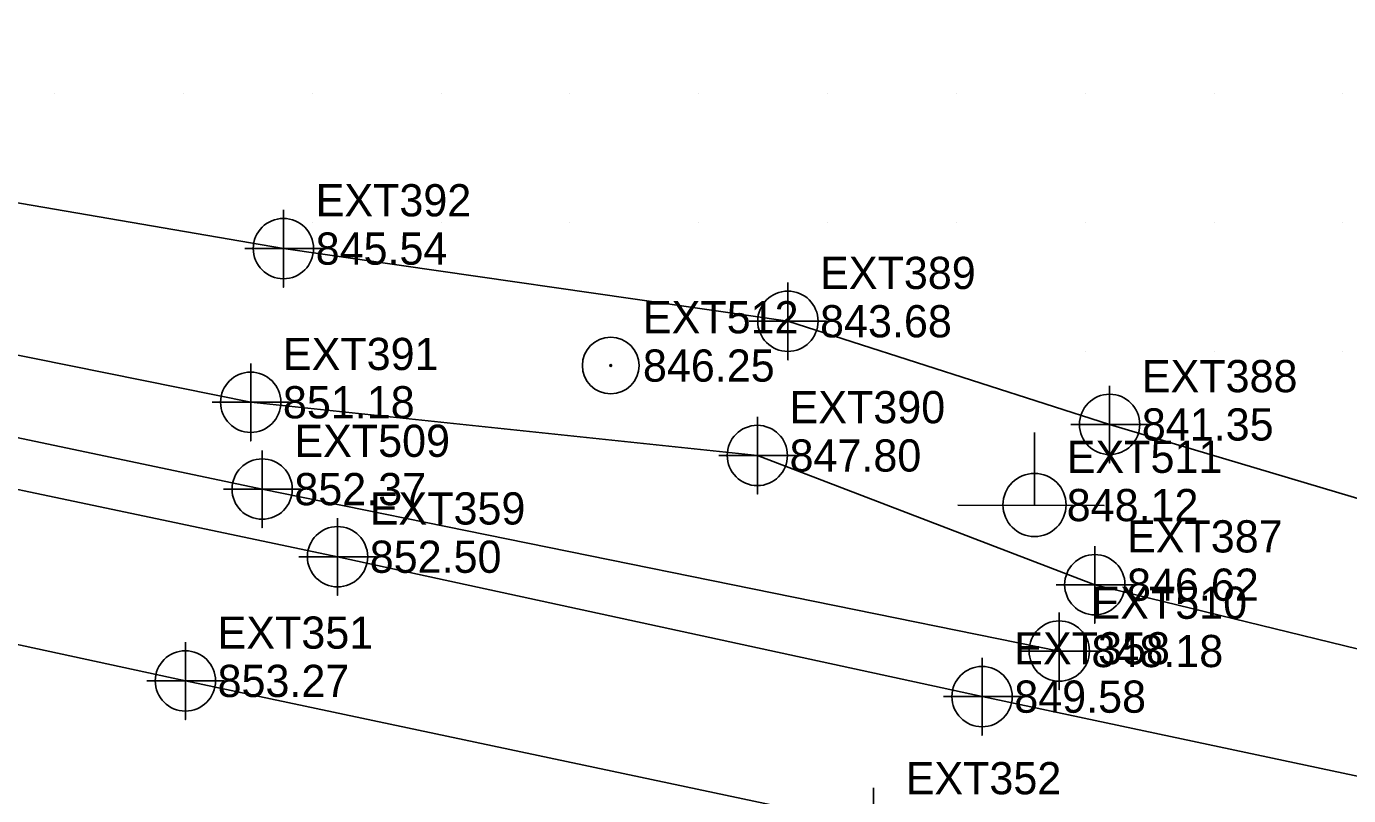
# Model space of a CAD drawing. Extents: x 1762120 to 1766775, y 709485 to 712965.
# Drawn here: x 1762807.8 to 1762910.4, y 712625.5 to 712685.2 of the extents above; entities that cross this region are included whole.
import ezdxf

# ---------------------------------------------------------------- set-up
doc = ezdxf.new("R2010")
doc.units = 0
for name, color, linetype in [('Exist DTM Breakline', 7, 'Continuous'), ('Exist DTM Breakline Cogo Elevation', 7, 'Continuous'), ('Exist DTM Breakline Cogo Number', 7, 'Continuous'), ('Exist DTM Breakline Cogo Point CELL', 7, 'Continuous'), ('Exist DTM Crownline', 7, 'Continuous'), ('Exist DTM Crownline Cogo Elevation', 7, 'Continuous'), ('Exist DTM Crownline Cogo Number', 7, 'Continuous'), ('Exist DTM Crownline Cogo Point CELL', 7, 'Continuous'), ('Exist DTM Drainline', 7, 'Continuous'), ('Exist DTM Drainline Cogo Elevation', 7, 'Continuous'), ('Exist DTM Drainline Cogo Number', 7, 'Continuous'), ('Exist DTM Drainline Cogo Point CELL', 7, 'Continuous'), ('Exist DTM QL2 LIDAR Elevation Point', 7, 'Continuous'), ('Exist Property Iron Pin CELL', 7, 'Continuous'), ('Exist Property Iron Pin Cogo Elevation', 7, 'Continuous'), ('Exist Property Iron Pin Cogo Number', 7, 'Continuous'), ('Exist Roads EOP', 7, 'Continuous'), ('Exist Roads EOP Cogo Elevation', 7, 'Continuous'), ('Exist Roads EOP Cogo Number', 7, 'Continuous'), ('Exist Roads EOP Cogo Point CELL', 7, 'Continuous'), ('Exist Utilities Gas UG Line SUE LOS C', 7, 'Continuous'), ('Exist Utilities Gas UG Line SUE LOS C Cogo Elevation', 7, 'Continuous'), ('Exist Utilities Gas UG Line SUE LOS C Cogo Number', 7, 'Continuous'), ('Exist Utilities Gas UG Line SUE LOS C Cogo Point CELL', 7, 'Continuous'), ('Exist Utilities Power Joint Use Telephone CELL', 7, 'Continuous'), ('Exist Utilities Power Joint Use Telephone Cogo Elevation', 7, 'Continuous'), ('Exist Utilities Power Joint Use Telephone Cogo Number', 7, 'Continuous')]:
    doc.layers.add(name, color=color, linetype=linetype)

msp = doc.modelspace()

# ---------------------------------------------------------------- linework, layer by layer
at = {"layer": 'Exist DTM Breakline'}
msp.add_lwpolyline([(1762979.15, 712640.9), (1762976.96, 712642.93), (1762967.83, 712644.52), (1762963.46, 712633.49), (1762955.46, 712627.84), (1762924.04, 712633.75), (1762890.74, 712641.89), (1762864.55, 712651.92), (1762825.23, 712656.05), (1762777.55, 712665.69), (1762763.53, 712670.44)], dxfattribs=at)
at = {"layer": 'Exist DTM Breakline Cogo Point CELL'}
for points in [[(1762825.23, 712659.05), (1762825.23, 712653.05), (1762825.23, 712656.05), (1762828.23, 712656.05), (1762822.23, 712656.05)], [(1762864.55, 712654.92), (1762864.55, 712648.92), (1762864.55, 712651.92), (1762867.55, 712651.92), (1762861.55, 712651.92)], [(1762890.74, 712644.89), (1762890.74, 712638.89), (1762890.74, 712641.89), (1762893.74, 712641.89), (1762887.74, 712641.89)]]:
    msp.add_lwpolyline(points, dxfattribs=at)
for centre in [(1762825.23, 712656.05), (1762864.55, 712651.92), (1762890.74, 712641.89)]:
    msp.add_circle(centre, 2.34, dxfattribs=at)
at = {"layer": 'Exist DTM Crownline'}
msp.add_lwpolyline([(1762166.55, 712774.69), (1762217.29, 712763.93), (1762266.93, 712753.16), (1762315.99, 712742.65), (1762361.3, 712733.13), (1762409.52, 712722.71), (1762461.51, 712711.51), (1762512.12, 712700.31), (1762561, 712689.86), (1762611.48, 712678.84), (1762663.77, 712667.96), (1762715.27, 712656.97), (1762767.73, 712645.75), (1762820.16, 712634.42), (1762873.56, 712623.12), (1762907.32, 712615.87), (1762954.84, 712607.61), (1762970.66, 712604.72)], dxfattribs=at)
at = {"layer": 'Exist DTM Crownline Cogo Point CELL'}
for points in [[(1762820.16, 712637.42), (1762820.16, 712631.42), (1762820.16, 712634.42), (1762823.16, 712634.42), (1762817.16, 712634.42)], [(1762873.56, 712626.12), (1762873.56, 712620.12), (1762873.56, 712623.12), (1762876.56, 712623.12), (1762870.56, 712623.12)]]:
    msp.add_lwpolyline(points, dxfattribs=at)
msp.add_circle((1762820.16, 712634.42), 2.34, dxfattribs=at)
at = {"layer": 'Exist DTM Drainline'}
msp.add_lwpolyline([(1762956.08, 712637.37), (1762926.01, 712644.16), (1762891.89, 712654.33), (1762866.92, 712662.34), (1762827.77, 712667.98), (1762778.65, 712676.42), (1762761.22, 712676.6), (1762740.51, 712682.25), (1762728.17, 712682.65)], dxfattribs=at)
at = {"layer": 'Exist DTM Drainline Cogo Point CELL'}
for points in [[(1762827.77, 712670.98), (1762827.77, 712664.98), (1762827.77, 712667.98), (1762830.77, 712667.98), (1762824.77, 712667.98)], [(1762866.92, 712665.34), (1762866.92, 712659.34), (1762866.92, 712662.34), (1762869.92, 712662.34), (1762863.92, 712662.34)], [(1762891.89, 712657.33), (1762891.89, 712651.33), (1762891.89, 712654.33), (1762894.89, 712654.33), (1762888.89, 712654.33)]]:
    msp.add_lwpolyline(points, dxfattribs=at)
for centre in [(1762827.77, 712667.98), (1762866.92, 712662.34), (1762891.89, 712654.33)]:
    msp.add_circle(centre, 2.34, dxfattribs=at)
at = {"layer": 'Exist DTM QL2 LIDAR Elevation Point'}
for p, q in [((1762810, 712680), (1762810, 712680)), ((1762820, 712680), (1762820, 712680)), ((1762830, 712680), (1762830, 712680)), ((1762840, 712680), (1762840, 712680)), ((1762850, 712680), (1762850, 712680)), ((1762860, 712680), (1762860, 712680)), ((1762870, 712680), (1762870, 712680)), ((1762880, 712680), (1762880, 712680)), ((1762890, 712680), (1762890, 712680)), ((1762900, 712680), (1762900, 712680)), ((1762910, 712680), (1762910, 712680)), ((1762830, 712670), (1762830, 712670)), ((1762840, 712670), (1762840, 712670)), ((1762850, 712670), (1762850, 712670)), ((1762860, 712670), (1762860, 712670)), ((1762870, 712670), (1762870, 712670)), ((1762880, 712670), (1762880, 712670)), ((1762890, 712670), (1762890, 712670)), ((1762900, 712670), (1762900, 712670)), ((1762910, 712670), (1762910, 712670)), ((1762890, 712660), (1762890, 712660)), ((1762900, 712660), (1762900, 712660)), ((1762910, 712660), (1762910, 712660))]:
    msp.add_line(p, q, dxfattribs=at)
at = {"layer": 'Exist Property Iron Pin CELL'}
for radius in [2.2, 0.0707]:
    msp.add_circle((1762853.17, 712658.9), radius, dxfattribs=at)
at = {"layer": 'Exist Roads EOP'}
msp.add_lwpolyline([(1762972.64, 712616.33), (1762930.48, 712622.91), (1762881.99, 712633.2), (1762831.97, 712644.06), (1762782.82, 712654.41), (1762735.74, 712664.41), (1762686.68, 712675.53), (1762639.56, 712685.27), (1762589.4, 712696.15), (1762546.23, 712705.49), (1762496.4, 712716.08), (1762446.15, 712726.9), (1762396.23, 712737.69), (1762346.43, 712748.23), (1762295.97, 712759.18), (1762245.1, 712770.1), (1762193.68, 712780.97), (1762169, 712786.42)], dxfattribs=at)
at = {"layer": 'Exist Roads EOP Cogo Point CELL'}
for points in [[(1762831.97, 712647.06), (1762831.97, 712641.06), (1762831.97, 712644.06), (1762834.97, 712644.06), (1762828.97, 712644.06)], [(1762881.99, 712636.2), (1762881.99, 712630.2), (1762881.99, 712633.2), (1762884.99, 712633.2), (1762878.99, 712633.2)]]:
    msp.add_lwpolyline(points, dxfattribs=at)
for centre in [(1762831.97, 712644.06), (1762881.99, 712633.2)]:
    msp.add_circle(centre, 2.34, dxfattribs=at)
at = {"layer": 'Exist Utilities Gas UG Line SUE LOS C'}
msp.add_lwpolyline([(1762186.21, 712786.58), (1762241.95, 712774.53), (1762368.98, 712745.66), (1762446.66, 712730.32), (1762499.18, 712718.67), (1762560.33, 712705.06), (1762614.27, 712693.34), (1762654.57, 712685.66), (1762695.77, 712676.76), (1762747.57, 712665.85), (1762826.12, 712649.31), (1762887.98, 712636.74)], dxfattribs=at)
at = {"layer": 'Exist Utilities Gas UG Line SUE LOS C Cogo Point CELL'}
for points in [[(1762826.12, 712652.31), (1762826.12, 712646.31), (1762826.12, 712649.31), (1762829.12, 712649.31), (1762823.12, 712649.31)], [(1762887.98, 712639.74), (1762887.98, 712633.74), (1762887.98, 712636.74), (1762890.98, 712636.74), (1762884.98, 712636.74)]]:
    msp.add_lwpolyline(points, dxfattribs=at)
for centre in [(1762826.12, 712649.31), (1762887.98, 712636.74)]:
    msp.add_circle(centre, 2.34, dxfattribs=at)
at = {"layer": 'Exist Utilities Power Joint Use Telephone CELL'}
msp.add_line((1762886.06, 712648.07), (1762886.06, 712648.07), dxfattribs=at)
msp.add_lwpolyline([(1762880.12, 712648.07), (1762891.46, 712648.04), (1762886.06, 712648.05), (1762886.06, 712653.7)], dxfattribs=at)
msp.add_circle((1762886.06, 712648.08), 2.45, dxfattribs=at)

# ---------------------------------------------------------------- texts
at = {"layer": 'Exist DTM Breakline Cogo Elevation'}
for s, p in [('851.18', (1762827.73, 712654.8)), ('847.80', (1762867.05, 712650.67)), ('846.62', (1762893.24, 712640.64))]:
    msp.add_text(s, height=2.5, dxfattribs=at).set_placement(p)
at = {"layer": 'Exist DTM Breakline Cogo Number'}
for s, p in [('EXT391', (1762827.73, 712658.55)), ('EXT390', (1762867.05, 712654.42)), ('EXT387', (1762893.24, 712644.39))]:
    msp.add_text(s, height=2.5, dxfattribs=at).set_placement(p)
at = {"layer": 'Exist DTM Crownline Cogo Elevation'}
msp.add_text('853.27', height=2.5, dxfattribs=at).set_placement((1762822.66, 712633.17))
at = {"layer": 'Exist DTM Crownline Cogo Number'}
for s, p in [('EXT351', (1762822.66, 712636.92)), ('EXT352', (1762876.06, 712625.62))]:
    msp.add_text(s, height=2.5, dxfattribs=at).set_placement(p)
at = {"layer": 'Exist DTM Drainline Cogo Elevation'}
for s, p in [('845.54', (1762830.27, 712666.73)), ('843.68', (1762869.42, 712661.09)), ('841.35', (1762894.39, 712653.08))]:
    msp.add_text(s, height=2.5, dxfattribs=at).set_placement(p)
at = {"layer": 'Exist DTM Drainline Cogo Number'}
for s, p in [('EXT392', (1762830.27, 712670.48)), ('EXT389', (1762869.42, 712664.84)), ('EXT388', (1762894.39, 712656.83))]:
    msp.add_text(s, height=2.5, dxfattribs=at).set_placement(p)
at = {"layer": 'Exist Property Iron Pin Cogo Elevation'}
msp.add_text('846.25', height=2.5, dxfattribs=at).set_placement((1762855.67, 712657.65))
at = {"layer": 'Exist Property Iron Pin Cogo Number'}
msp.add_text('EXT512', height=2.5, dxfattribs=at).set_placement((1762855.67, 712661.4))
at = {"layer": 'Exist Roads EOP Cogo Elevation'}
for s, p in [('852.50', (1762834.47, 712642.81)), ('849.58', (1762884.49, 712631.95))]:
    msp.add_text(s, height=2.5, dxfattribs=at).set_placement(p)
at = {"layer": 'Exist Roads EOP Cogo Number'}
for s, p in [('EXT359', (1762834.47, 712646.56)), ('EXT358', (1762884.49, 712635.7))]:
    msp.add_text(s, height=2.5, dxfattribs=at).set_placement(p)
at = {"layer": 'Exist Utilities Gas UG Line SUE LOS C Cogo Elevation'}
for s, p in [('852.37', (1762828.62, 712648.06)), ('848.18', (1762890.48, 712635.49))]:
    msp.add_text(s, height=2.5, dxfattribs=at).set_placement(p)
at = {"layer": 'Exist Utilities Gas UG Line SUE LOS C Cogo Number'}
for s, p in [('EXT509', (1762828.62, 712651.81)), ('EXT510', (1762890.48, 712639.24))]:
    msp.add_text(s, height=2.5, dxfattribs=at).set_placement(p)
at = {"layer": 'Exist Utilities Power Joint Use Telephone Cogo Elevation'}
msp.add_text('848.12', height=2.5, dxfattribs=at).set_placement((1762888.56, 712646.82))
at = {"layer": 'Exist Utilities Power Joint Use Telephone Cogo Number'}
msp.add_text('EXT511', height=2.5, dxfattribs=at).set_placement((1762888.56, 712650.57))

doc.saveas('drawing.dxf')
